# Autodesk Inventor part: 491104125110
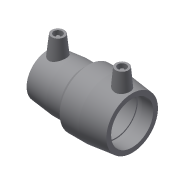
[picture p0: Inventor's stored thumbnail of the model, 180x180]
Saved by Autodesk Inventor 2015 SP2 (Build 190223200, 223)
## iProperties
Created: 2017-06
Part Number: 491104125110
Material: Generic
Description: PLASSON REDUCING COUPLER 125-110
Document SubType Name: Modeling
Designer: KIM
Mass: 54.8237 g
Surface Area: 155.252 cm^2
Volume: 54.8237 cm^3
Density: 1 g/cm^3
Appearance: Default
Author: KIM
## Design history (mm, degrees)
derived "491104.ipt"
feature "Solid1::491104.ipt"
tag "TaggingFeature1"
body "Solid1"
other parameters: "d0" = 171, "d2" = 141, "d3" = 78, "d4" = 46.8, "d5" = 126.9, "d8" = 168 deg, "d10" = 31.2, "d11" = 10.4, "d13" = 171, "d14" = 17.6296, "d15" = 78, "d19" = 3.9, "d20" = 168 deg, "d22" = 108.92847, "d25" = 135 deg, "d30" = 15, "d31" = 59.85, "d34" = 6 deg, "d35" = 15, "d38" = 19.5, "d39" = 5 deg, "d41" = 4, "d42" = 14, "d43" = 0, "d45" = 4, "d46" = 14, "d47" = 0, "d48" = 141, "d49" = 125, "d50" = 158, "d52" = 99, "d53" = 34, "d54" = 11.33333, "d55" = 168 deg, "d56" = 51, "d57" = 85, "d58" = 142.2, "d59" = 3.9, "d60" = 135 deg, "d61" = 88, "d62" = 15, "d64" = 4, "d66" = 5 deg, "d67" = 14, "d68" = 0, "d69" = 59.85, "d70" = 141, "d71" = 158, "d73" = 148.52, "d76" = 3.9, "d77" = 168 deg, "d78" = 125, "d79" = 3.9, "d80" = 85, "d81" = 99, "d82" = 132.54, "d83" = 120 deg, "d88" = 15, "d89" = 19.25, "d90" = 5 deg, "d92" = 4, "d93" = 14, "d94" = 0, "d95" = 3, "d96" = 0, "d97" = 3, "d98" = 0, "d99" = 22.62, "d100" = 5.655, "d101" = 128.5638, "d102" = 20 deg, "d103" = 24.65, "d104" = 6.1625, "d105" = 144.0644, "d106" = 3.60705, "d107" = 3, "d108" = 0, "d109" = 3, "d110" = 0, "L_" = 171, "L_2" = 78, "D_1" = 141, "d_2" = 12, "L_1" = 85, "d_" = 125, "A_" = 88, "D_" = 158
